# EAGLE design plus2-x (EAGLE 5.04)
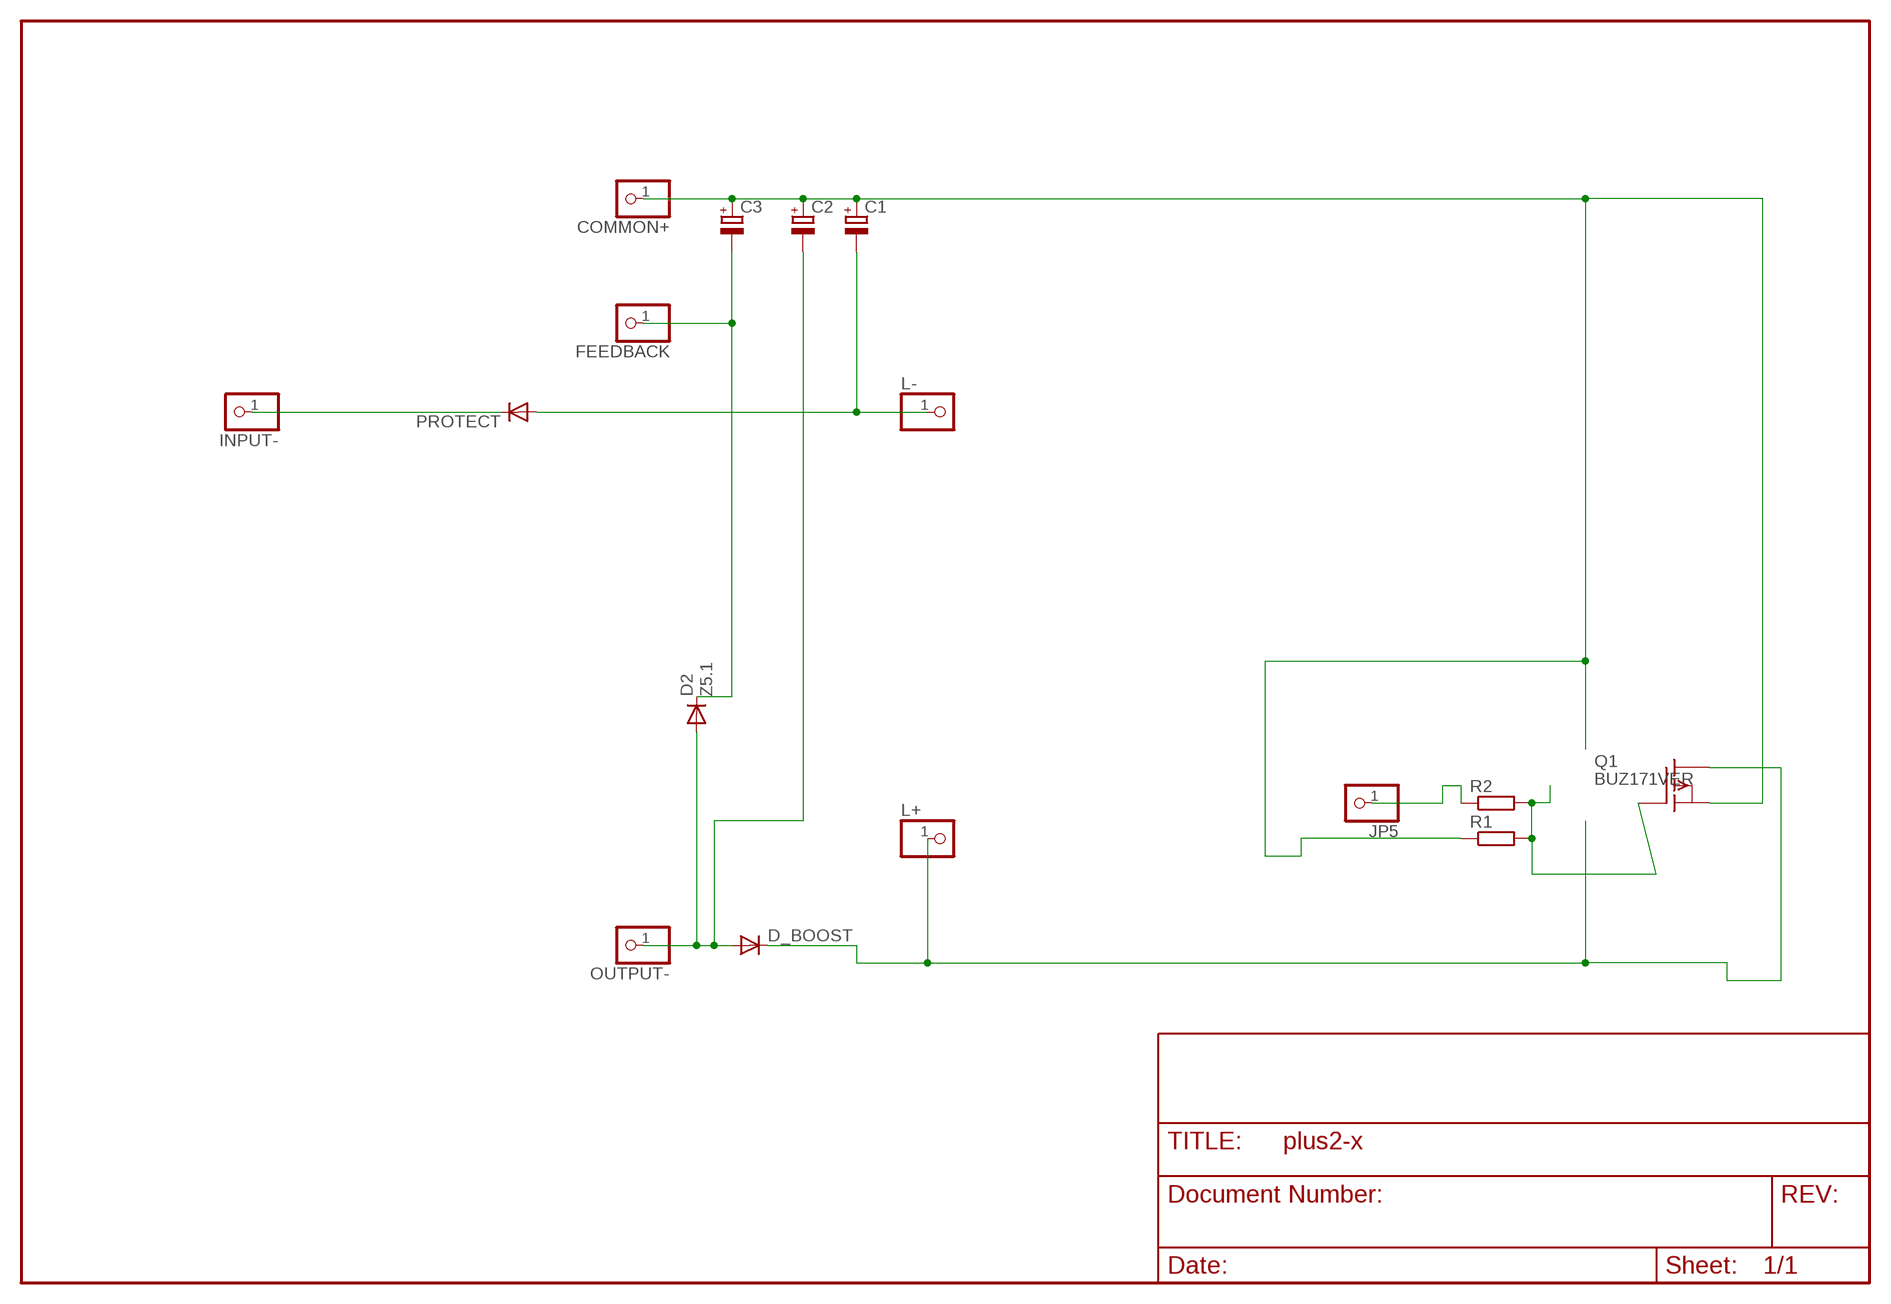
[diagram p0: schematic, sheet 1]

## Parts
C1  CPOL-EUE2.5-7  [E2,5-7]
C2  CPOL-EUE2.5-7  [E2,5-7]
C3  CPOL-EUE2-4  [E2-4]
COMMON+  PINHD-1X1  [1X01]
D2  Z5.1  DIODE-D-12.5  [D-12.5]
D_BOOST  DIODE-D-10  [D-10]
FEEDBACK  PINHD-1X1  [1X01]
INPUT-  PINHD-1X1  [1X01]
JP5  PINHD-1X1  [1X01]
L+  PINHD-1X1  [1X01]
L-  PINHD-1X1  [1X01]
OUTPUT-  PINHD-1X1  [1X01]
PROTECT  DIODE-D-5  [D-5]
Q1  BUZ171VER  [TO220V]
R1  R-EU_0204/2V  [0204V]
R2  R-EU_0204/2V  [0204V]

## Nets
HOTSPOT: D_BOOST.C L+.1 Q1.2(D)
N$1: Q1.1(G) R1.2 R2.2
N$2: C1.- L-.1 PROTECT.A
N$4: C1.+ C2.+ C3.+ COMMON+.1 Q1.3(S) R1.1
N$5: C2.- D2.A D_BOOST.A OUTPUT-.1
N$8: INPUT-.1 PROTECT.C
N$9: C3.- D2.C FEEDBACK.1
PULS: JP5.1 R2.1

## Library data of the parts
C1-C3 = rcl(2):CPOL-EU: POLARIZED CAPACITOR, European symbol
COMMON+ FEEDBACK INPUT- JP5 L+ L- OUTPUT- = pinhead:PINHD-1X1: PIN HEADER
D2 D_BOOST PROTECT = diode:DIODE-: DIODE
Q1 = transistor-fet:BUZ171: P-Channel Enhancement MOSFET -50V; 7A; 0,4Ohm
R1 R2 = rcl-2:R-EU_: RESISTOR, European symbol

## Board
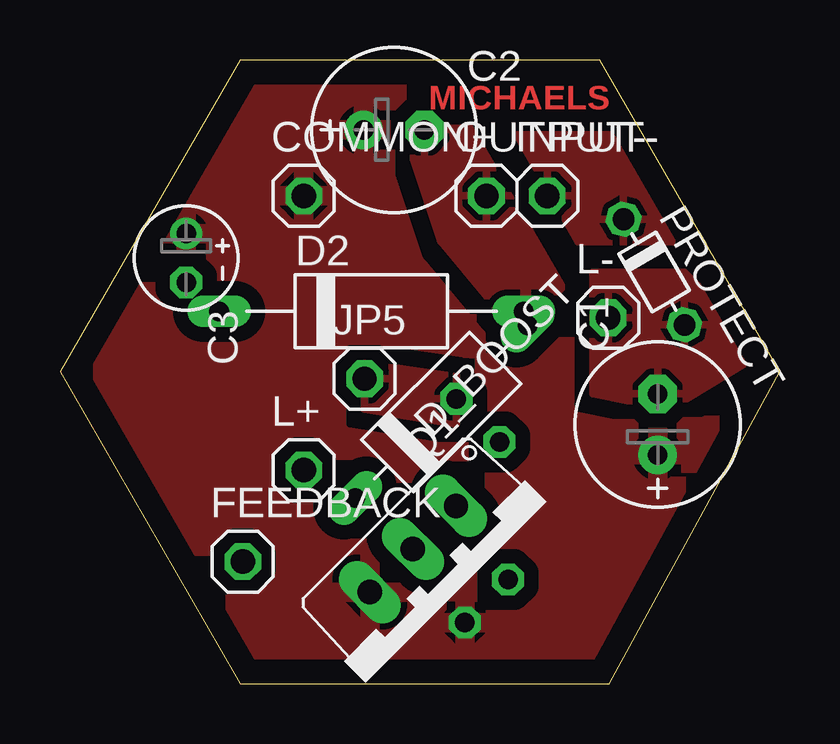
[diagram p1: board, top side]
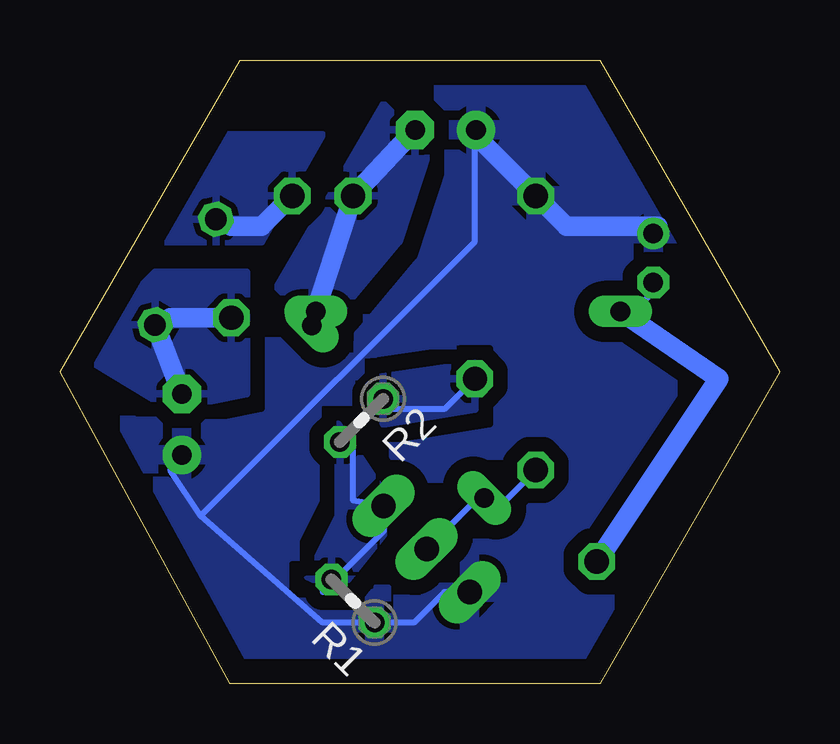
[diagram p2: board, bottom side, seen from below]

Size 30 x 25.98 mm. Coordinates in mm from the lower left corner, seen from the top.
Outline: 7.5,0 22.9,0 30,12.99 22.5,25.98 7.5,25.98 0,12.99 7.5,0
Copper layers (1*16): Top 0.035mm / dielectric 1.5mm / Bottom 0.035mm
Design rules "default": minimum track width 10mil, minimum drill 24mil, track to track 8mil, track to pad 8mil, pad to pad 8mil, via to via 8mil, smd to smd 8mil, copper to edge 40mil, drill to drill 8mil, minimum pad ring 10mil, minimum via ring 8mil, stop-mask expansion 4mil, vias tented up to drill 0mil, thermal gap 10mil

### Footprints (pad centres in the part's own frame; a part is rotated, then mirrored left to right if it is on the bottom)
E2,5-7 = drill 0.813 pad 1.6 round: + -1.27,0 | drill 0.813 pad 1.6 octagon: - 1.27,0
E2-4 = drill 0.813 pad 1.27 round: + -1.016,0 | drill 0.813 pad 1.27 octagon: - 1.016,0
1X01 = drill 1.016 octagon: 1 0,0
D-12.5 = drill 0.813 long: A 6.35,0; C -6.35,0
D-10 = drill 0.813 long: A 5.08,0; C -5.08,0
D-5 = drill 0.9 octagon: A 2.54,0; C -2.54,0
TO220V = drill 1.016 long: 1 -2.54,-2.54; 2 0,-2.54; 3 2.54,-2.54
0204V = drill 0.813 octagon: 1 -1.27,0; 2 1.27,0

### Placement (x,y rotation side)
C1  24.92,10.79 90 top
C2  13.93,23.07 0 top
C3  5.26,17.73 270 top
COMMON+  10.16,20.32 0 top
D2  12.99,15.5 0 top
D_BOOST  15.9,11.32 45 top
FEEDBACK  7.62,5.08 0 top
INPUT-  20.32,20.32 0 top
JP5  12.7,12.7 0 top
L+  10.16,8.89 0 top
L-  22.86,15.24 0 top
OUTPUT-  17.78,20.32 0 top
PROTECT  24.77,17.14 300 top
Q1  16.51,3.81 225 top
R1  17.78,3.44 135 bottom
R2  17.43,10.96 225 bottom

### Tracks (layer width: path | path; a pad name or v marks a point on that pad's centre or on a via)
HOTSPOT
  Bottom 0.254: Q1.2 13.97,6.35 12.7,7.62 D_BOOST.C 11.43,7.62 L+.1
N$1
  Bottom 0.254: R1.2 19.05,3.81 16.51,6.35 Q1.1 17.78,7.62 17.78,10.16 R2.2
  pour Bottom (isolate 0.61, rank 2): 18.41,10.79 18.41,6.99 19.68,4.45 18.41,3.81 15.88,6.99
N$2
  Bottom 0.254: PROTECT.A 25.4,15.24
  Bottom 0.813: C1.- PROTECT.A | 25.4,15.24 L-.1
  pour Bottom (isolate 0.61): 22.23,17.14 26.04,17.14 27.3,15.88 28.57,13.34 25.4,11.43 22.23,12.06
  pour Top (isolate 0.61): 22.23,17.14 26.04,17.14 27.3,15.88 28.57,13.34 25.4,11.43 22.23,12.06
N$4
  Bottom 0.254: 5.08,19.05 C3.+ | Q1.3 13.97,3.81 15.24,2.54 16.51,2.54 R1.1 19.05,2.54 24.13,6.99 | 24.13,6.99 25.4,8.89 C1.+ | 24.13,6.99 12.7,18.41 12.7,22.86 C2.+
  Bottom 0.813: 5.08,19.05 8.89,19.05 COMMON+.1 12.7,22.86
  pour Bottom (isolate 0.61, rank 3): 7.62,25.4 22.86,25.4 30.48,12.7 22.86,0 7.62,0 0,12.7
  pour Top (isolate 0.61, rank 3): 7.62,25.4 22.86,25.4 30.48,12.7 22.86,0 7.62,0 0,12.7
N$5
  Bottom 0.406: D_BOOST.A 20.32,15.24 D2.A
  Bottom 0.813: C2.- OUTPUT-.1 D2.A
  pour Bottom (isolate 0.61): 14.61,22.23 15.88,18.41 19.05,14.61 20.95,16.51 16.51,24.13
  pour Top (isolate 0.61): 14.61,22.23 15.88,18.41 19.05,14.61 20.95,16.51 16.51,24.13
N$8
  Bottom 0.254: 22.86,19.05 PROTECT.C
  Bottom 0.813: 22.86,19.05 21.59,19.05 INPUT-.1
  pour Bottom (isolate 0.61, rank 2): 19.05,22.86 23.5,22.86 26.04,18.41 21.59,18.41
  pour Top (isolate 0.61, rank 2): 19.05,22.86 23.5,22.86 26.04,18.41 21.59,18.41
N$9
  Bottom 0.254: C3.- 5.08,16.51 6.35,15.24 D2.C
  Bottom 0.813: FEEDBACK.1 2.54,12.7 D2.C
PULS
  Bottom 0.254: JP5.1 13.97,11.43 16.51,11.43 R2.1
  pour Bottom (isolate 0.61): 12.7,13.34 17.14,12.7 16.51,10.79 12.7,11.43
  pour Top (isolate 0.61): 12.7,13.34 17.14,12.7 16.51,10.79 12.7,11.43

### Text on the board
Top: MICHAELS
